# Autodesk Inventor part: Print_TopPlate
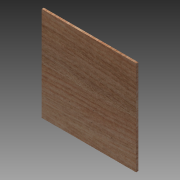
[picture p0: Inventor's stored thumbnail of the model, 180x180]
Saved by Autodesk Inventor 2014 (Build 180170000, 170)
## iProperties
Created: 2013-12
Part Number: Print_TopPlate
Material: Birch
Document SubType Name: Modeling
Designer: Bram
Density: 0.512 g/cm^3
Appearance: Birch - Natural Medium Gloss
Author: Bram
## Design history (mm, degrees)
sketch "Sketch1"
  geometry: L1 (0, 0)-(225, 0); L2 (225, 0)-(225, 225); L3 (225, 225)-(0, 225); L4 (0, 225)-(0, 0)
  constraints: 8 end point, 2 parallel, 1 horizontal, 1 perpendicular
  dimensions: "d0" = 225 distance of L3.end L2.end; "d1" = 225 distance of L2.end L1.end
extrude "Extrusion1" new body sketch "Sketch1" distance "d2" = 5; taper "d3" = 0 deg
body "Solid1"
